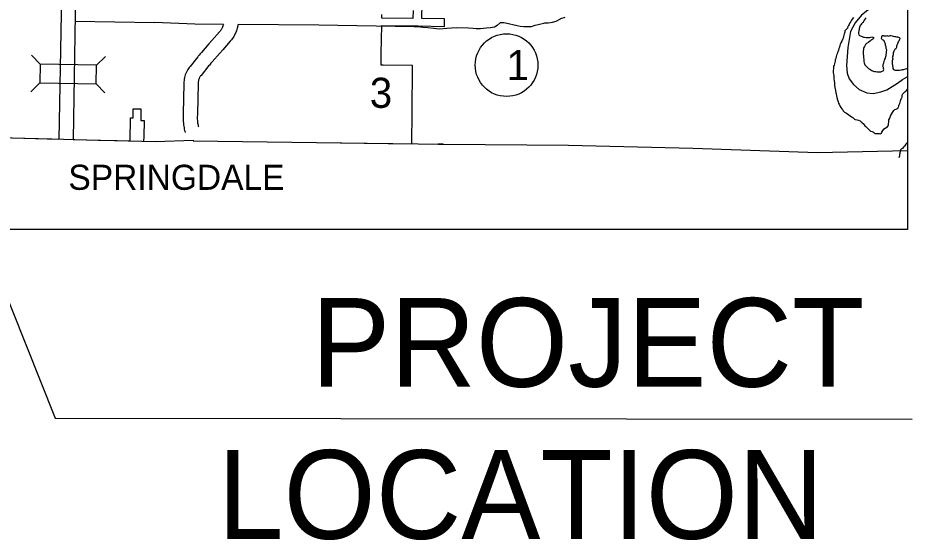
# Model space of a CAD drawing. Extents: x 670147 to 673275, y 705573 to 707613.
# Drawn here: x 670561.9 to 670844.4, y 706894.6 to 707059.4 of the extents above; entities that cross this region are included whole.
import ezdxf

# ---------------------------------------------------------------- set-up
doc = ezdxf.new("R2010")
doc.units = 0
for name, color, linetype in [('10', 7, 'Continuous'), ('15', 7, 'Continuous'), ('2', 7, 'Continuous'), ('20', 7, 'Continuous'), ('27', 7, 'Continuous'), ('3', 7, 'Continuous'), ('6', 7, 'Continuous'), ('9', 7, 'Continuous'), ('Default', 7, 'Continuous'), ('R_NoPlot', 7, 'Continuous')]:
    doc.layers.add(name, color=color, linetype=linetype)

msp = doc.modelspace()

# ---------------------------------------------------------------- linework, layer by layer
at = {"layer": '10'}
for points in [[(670714.38, 707057.94), (670714.95, 707057.96), (670715.35, 707057.98), (670715.96, 707057.82), (670719.66, 707056.95), (670720.57, 707056.8), (670721.72, 707056.67), (670722.83, 707056.67), (670724.1, 707056.72), (670725.29, 707057.05), (670726.28, 707057.33), (670728.01, 707057.78), (670728.36, 707057.87), (670728.75, 707057.89), (670729.38, 707057.86), (670730.13, 707057.94), (670730.81, 707058.02), (670731.9, 707058.41), (670733.05, 707059.03), (670733.26, 707059.12), (670733.45, 707059.2), (670734.82, 707059.61)], [(670580.04, 707058.39), (670605.11, 707057.96)], [(670626.83, 707057.3), (670617.83, 707057.37), (670605.05, 707057.96)], [(670626.61, 707056.66), (670626.51, 707056.43), (670626.42, 707056.24), (670626.33, 707056.05), (670626.22, 707055.86), (670626.09, 707055.65), (670625.95, 707055.44), (670625.79, 707055.24), (670625.71, 707055.13), (670625.6, 707055.01), (670623.21, 707052.28), (670622.27, 707051.22), (670619.86, 707048.47), (670619.46, 707048.01), (670619.17, 707047.66), (670618.89, 707047.32), (670618.75, 707047.15), (670616.28, 707044.09), (670616.17, 707043.95), (670616.02, 707043.76), (670615.78, 707043.43), (670615.56, 707043.08), (670615.34, 707042.71), (670615.14, 707042.3), (670614.95, 707041.88), (670614.79, 707041.44), (670614.66, 707041), (670614.55, 707040.55), (670614.46, 707040.1), (670614.4, 707039.64), (670614.37, 707039.2), (670614.37, 707039.05), (670614.37, 707039.04), (670614.36, 707038.97), (670614.35, 707038.42), (670614.24, 707034.26), (670614.22, 707033.72), (670614.11, 707029.41), (670614.09, 707028.82), (670614.08, 707028.34), (670614.07, 707027.8), (670614.09, 707027.24), (670614.12, 707026.68), (670614.17, 707026.16)], [(670626.83, 707057.3), (670626.68, 707056.85), (670626.58, 707056.58)], [(670631.45, 707057.27), (670631.18, 707056.18), (670631.07, 707055.78), (670630.93, 707055.36), (670630.79, 707055)], [(670714.38, 707057.94), (670713.29, 707056.97), (670712.43, 707056.47), (670711.21, 707056.27), (670709.96, 707056.11), (670708, 707055.97), (670706.7, 707055.99), (670705.69, 707056.05), (670704.19, 707056.2), (670700.59, 707056.28), (670698.91, 707056.15), (670697.35, 707056.02), (670695.23, 707055.89), (670694.16, 707055.92), (670693.15, 707056.02), (670691.36, 707056.23), (670689.83, 707056.37), (670689.08, 707056.48), (670687.08, 707056.61), (670656.97, 707057.07), (670631.45, 707057.27)], [(670630.76, 707054.91), (670630.63, 707054.6), (670630.46, 707054.25), (670630.29, 707053.91), (670630.09, 707053.57), (670629.86, 707053.19), (670629.6, 707052.82), (670629.34, 707052.47), (670629.17, 707052.25), (670629, 707052.06), (670626.59, 707049.31), (670625.65, 707048.25), (670623.25, 707045.51), (670622.89, 707045.09), (670622.64, 707044.79), (670622.38, 707044.48), (670622.26, 707044.33), (670619.78, 707041.26), (670619.69, 707041.15), (670619.62, 707041.06), (670619.5, 707040.89), (670619.4, 707040.74), (670619.31, 707040.57), (670619.21, 707040.39), (670619.13, 707040.2), (670619.06, 707040), (670619, 707039.8), (670618.95, 707039.6), (670618.91, 707039.4), (670618.88, 707039.19), (670618.87, 707038.96), (670618.86, 707038.92), (670618.86, 707038.85), (670618.85, 707038.3), (670618.74, 707034.14), (670618.72, 707033.6), (670618.61, 707029.29), (670618.59, 707028.69), (670618.58, 707028.25), (670618.57, 707027.83), (670618.58, 707027.42), (670618.61, 707027.01), (670618.65, 707026.57)], [(670614.17, 707026.09), (670614.23, 707025.66), (670614.3, 707025.2), (670614.38, 707024.74), (670614.47, 707024.28), (670614.58, 707023.83), (670614.7, 707023.4)], [(670618.64, 707026.64), (670618.69, 707026.27), (670618.74, 707025.94), (670618.8, 707025.6), (670618.87, 707025.27), (670618.92, 707025.04)], [(670614.71, 707023.37), (670614.72, 707023.33), (670614.76, 707023.18)]]:
    msp.add_lwpolyline(points, dxfattribs=at)
at = {"layer": '15'}
for points in [[(670576.52, 707129.64), (670576.32, 707100.63), (670575.55, 707060.68), (670574.89, 707021.12)], [(670581.02, 707129.6), (670580.82, 707100.57), (670580.05, 707060.6), (670579.39, 707021)]]:
    msp.add_lwpolyline(points, dxfattribs=at)
at = {"layer": '2'}
for points in [[(670842.89, 707067.82), (670842.6, 707067.64), (670836.57, 707064.43), (670833.58, 707063.2), (670831.77, 707062.54), (670830.37, 707061.79), (670828.34, 707060.25), (670826.36, 707057.83), (670824.91, 707055.1), (670824.08, 707050), (670823.59, 707044.36), (670823.89, 707041.99), (670824.47, 707040.18), (670825.82, 707038.37), (670827.66, 707036.84), (670830.09, 707035.76), (670832.09, 707035.54), (670834.44, 707036.01), (670836.33, 707036.7), (670839.7, 707038.77), (670841.3, 707040), (670842.82, 707040.76), (670842.89, 707040.79)], [(670483.51, 707023.32), (670498.06, 707023.16), (670537.81, 707022.16), (670574.89, 707021.12)], [(670579.39, 707021), (670605.42, 707020.34)], [(670605.42, 707020.34), (670617.29, 707020.81)], [(670617.29, 707020.81), (670617.29, 707020.62)], [(670617.29, 707020.62), (670656.28, 707020.03), (670696.3, 707019.49), (670735.86, 707019.17), (670775.08, 707018.25), (670814.5, 707016.94), (670842.89, 707017.55)]]:
    msp.add_lwpolyline(points, dxfattribs=at)
at = {"layer": '20'}
for p, q in [((670568.95, 707044.79), (670566.2, 707047.63)), ((670586.77, 707044.49), (670589.62, 707047.24)), ((670568.85, 707038.85), (670566.01, 707036.1)), ((670586.67, 707038.55), (670589.42, 707035.71))]:
    msp.add_line(p, q, dxfattribs=at)
msp.add_lwpolyline([(670568.85, 707038.85), (670586.67, 707038.55), (670586.77, 707044.49), (670568.95, 707044.79)], close=True, dxfattribs=at)
at = {"layer": '27'}
msp.add_circle((670716.27, 707044.49), 9.9, dxfattribs=at)
at = {"layer": '3'}
msp.add_lwpolyline([(670696.27, 707019.49), (670694.62, 707019.52)], dxfattribs=at)
at = {"layer": '6'}
for points in [[(670686.36, 707019.63), (670686.37, 707021.43), (670686.39, 707023.25), (670686.41, 707026.14), (670686.44, 707029.51), (670686.44, 707030.2), (670686.43, 707031.88), (670686.43, 707032.26), (670686.46, 707034.21), (670686.46, 707034.58), (670686.5, 707039.02), (670686.51, 707039.37), (670686.54, 707044.32), (670677.28, 707044.46), (670676.64, 707044.47), (670676.68, 707048.15), (670676.83, 707057.04), (670686.68, 707056.88), (670687.78, 707056.87), (670688.34, 707056.86), (670696.66, 707056.72), (670696.67, 707058.41), (670696.67, 707058.72), (670696.66, 707058.98), (670696.65, 707059.1), (670689.54, 707059.17), (670689.61, 707064.05)], [(670686.8, 707061.78), (670686.7, 707059.2), (670676.86, 707059.3), (670676.87, 707060.44)], [(670597.42, 707020.54), (670597.51, 707027.89), (670598.33, 707027.86), (670598.36, 707030.74), (670599.02, 707030.72), (670599.55, 707030.71), (670600.69, 707030.69), (670600.78, 707030.69), (670600.72, 707027.03), (670601.56, 707027.02), (670601.77, 707027.01), (670601.68, 707021.85), (670601.62, 707020.44)], [(670547.03, 707021.9), (670572.67, 707021.18), (670587.25, 707020.8), (670593.29, 707020.65), (670597.42, 707020.54)], [(670601.62, 707020.44), (670605.42, 707020.34), (670617.29, 707020.81), (670617.29, 707020.62), (670656.28, 707020.03), (670686.36, 707019.63)], [(670694.62, 707019.52), (670694.62, 707019.56), (670694.8, 707019.56), (670696.27, 707019.54), (670696.27, 707019.49)]]:
    msp.add_lwpolyline(points, dxfattribs=at)
at = {"layer": '9'}
for points in [[(670825.88, 707059.57), (670825.45, 707059.01), (670825.18, 707058.66), (670824.96, 707058.25), (670824.71, 707057.83), (670824.51, 707057.27)], [(670829.87, 707059.4), (670829.5, 707059.11), (670829.17, 707058.64), (670828.99, 707058.21), (670828.9, 707057.97), (670828.71, 707057.8), (670828.35, 707057.54)], [(670824.07, 707056.63), (670823.94, 707056.2), (670823.77, 707055.99), (670823.55, 707055.78), (670823.39, 707055.61), (670823.21, 707055.4), (670823.16, 707055.36), (670823.15, 707055.09), (670823.15, 707054.91), (670823.02, 707054.62), (670822.88, 707054.38), (670822.78, 707053.97), (670822.68, 707053.54), (670822.56, 707053.04), (670822.41, 707052.57), (670822.13, 707052.04), (670821.85, 707051.5), (670821.69, 707051.14), (670821.51, 707050.64), (670821.39, 707050.16), (670821.26, 707049.74), (670821.09, 707049.21), (670820.98, 707048.87), (670820.81, 707048.43), (670820.64, 707048.01), (670820.5, 707047.59), (670820.39, 707047.16), (670820.23, 707046.59), (670820.11, 707046.16), (670820.04, 707045.72), (670819.94, 707045.28), (670819.84, 707044.85), (670819.76, 707044.5), (670819.57, 707044.14), (670819.5, 707043.72), (670819.49, 707043.33), (670819.44, 707042.86), (670819.43, 707042.48), (670819.43, 707042.11), (670819.53, 707041.6), (670819.59, 707041.16), (670819.59, 707040.65), (670819.66, 707040.14), (670819.75, 707039.57), (670819.8, 707038.78), (670819.88, 707038.13), (670819.91, 707037.41), (670820.02, 707036.88), (670820.16, 707036.49), (670820.28, 707035.77), (670820.34, 707035.47), (670820.48, 707034.81), (670820.61, 707034.27), (670820.79, 707033.51), (670821.02, 707032.92), (670821.14, 707032.44), (670821.29, 707032.16), (670821.52, 707031.68), (670821.84, 707031.1), (670822.17, 707030.69), (670822.43, 707030.35), (670822.59, 707030.04), (670822.87, 707029.74), (670823, 707029.66), (670823.59, 707029.32), (670824.36, 707028.82), (670824.78, 707028.53), (670825.24, 707028.19), (670825.67, 707027.95), (670825.91, 707027.65), (670826.16, 707027.46), (670826.42, 707027.33), (670827, 707027.21), (670827.42, 707027.11), (670827.92, 707026.87), (670828.21, 707026.66), (670828.49, 707026.46), (670828.64, 707026.28), (670828.93, 707026.01), (670829.19, 707025.65), (670829.46, 707025.35), (670829.75, 707025.07), (670829.96, 707024.87), (670830.35, 707024.5), (670830.74, 707024.14), (670830.97, 707023.84), (670831.27, 707023.66), (670831.7, 707023.52), (670832.21, 707023.28), (670832.55, 707022.95), (670833.09, 707022.9), (670833.58, 707022.87), (670833.96, 707022.86), (670834.29, 707022.81), (670834.65, 707022.97), (670834.79, 707023.3), (670835.09, 707023.8), (670835.52, 707024.33), (670835.98, 707024.64), (670836.36, 707024.84), (670836.84, 707025.28)], [(670824.51, 707057.27), (670824.32, 707056.97), (670824.14, 707056.76), (670824.07, 707056.63)], [(670827.82, 707056.68), (670827.66, 707056.05), (670827.6, 707055.6), (670827.53, 707055.28), (670827.41, 707054.86), (670827.41, 707054.44), (670827.56, 707054.1), (670827.76, 707053.86), (670828.03, 707053.69), (670828.28, 707053.62), (670828.61, 707053.52), (670828.96, 707053.32), (670829.35, 707053.27), (670829.83, 707053.18), (670830.39, 707053.21), (670830.9, 707053.26), (670831.3, 707053.31), (670831.64, 707053.37), (670831.94, 707053.3), (670832.12, 707053.2), (670832.23, 707053.09), (670832.14, 707052.91), (670831.92, 707052.7), (670831.69, 707052.5), (670831.37, 707052.21), (670831.1, 707052.06), (670830.63, 707051.71), (670830.4, 707051.56), (670830.13, 707051.41), (670829.92, 707051.27), (670829.62, 707051.01), (670829.49, 707050.76), (670829.34, 707050.35), (670829.15, 707050.05), (670829.06, 707049.7), (670829.03, 707049.45), (670828.94, 707048.92), (670828.92, 707048.41), (670828.93, 707047.96), (670828.98, 707047.46), (670829, 707047.06), (670829.03, 707046.77), (670829.09, 707046.41), (670829.11, 707046.08), (670829.13, 707045.62), (670829.22, 707045.18), (670829.3, 707044.87), (670829.42, 707044.58), (670829.6, 707044.33), (670829.8, 707044.12), (670830.05, 707044), (670830.29, 707043.75), (670830.62, 707043.45), (670830.97, 707043.21), (670831.33, 707042.96), (670831.63, 707042.76), (670832.1, 707042.59), (670832.44, 707042.45), (670832.86, 707042.44), (670833.3, 707042.36), (670833.85, 707042.34), (670834.47, 707042.42), (670834.89, 707042.53), (670835.17, 707042.64), (670835.35, 707042.82), (670835.48, 707043.15), (670835.36, 707043.39), (670835.3, 707043.71), (670835.18, 707043.99), (670835.12, 707044.19), (670835.21, 707044.4), (670835.26, 707044.7), (670835.32, 707044.92), (670835.41, 707045.21), (670835.51, 707045.65), (670835.68, 707046.02), (670835.78, 707046.34), (670835.96, 707046.73), (670836.04, 707047.23), (670836.15, 707047.57), (670836.2, 707048), (670836.28, 707048.31), (670836.32, 707048.7), (670836.33, 707049.17), (670836.3, 707049.45), (670836.21, 707049.93), (670836.12, 707050.28), (670836.05, 707050.52), (670836.01, 707050.79), (670835.96, 707051.12), (670835.84, 707051.4), (670835.76, 707051.66), (670835.69, 707051.87), (670835.58, 707052.11), (670835.44, 707052.29), (670835.25, 707052.38), (670834.99, 707052.52), (670834.75, 707052.66), (670834.65, 707052.87), (670834.7, 707053.14), (670834.79, 707053.36)], [(670828.35, 707057.54), (670828.17, 707057.16), (670827.99, 707056.95), (670827.82, 707056.68)], [(670834.79, 707053.36), (670834.85, 707053.58), (670834.97, 707053.79), (670835.19, 707053.79), (670835.46, 707053.76), (670835.73, 707053.72), (670835.97, 707053.7), (670836.21, 707053.69), (670836.41, 707053.8), (670836.59, 707053.72), (670836.84, 707053.66), (670837.1, 707053.7), (670837.38, 707053.82), (670837.64, 707053.82), (670838.1, 707053.7), (670838.39, 707053.61), (670838.75, 707053.53), (670839.09, 707053.48), (670839.39, 707053.37), (670839.74, 707053.37), (670840.1, 707053.28), (670840.29, 707053.22), (670840.43, 707053.15), (670840.52, 707052.97), (670840.49, 707052.8), (670840.43, 707052.58), (670840.31, 707052.4), (670840.14, 707052.09), (670839.97, 707051.81), (670839.83, 707051.54), (670839.74, 707051.25), (670839.68, 707051.02), (670839.57, 707050.84), (670839.47, 707050.51), (670839.4, 707050.17), (670839.41, 707050), (670839.36, 707049.81), (670839.18, 707049.62), (670838.95, 707049.41), (670838.82, 707049.23), (670838.69, 707049.08), (670838.55, 707048.75), (670838.42, 707048.51), (670838.35, 707048.15), (670838.33, 707047.77), (670838.32, 707047.47), (670838.29, 707047.14), (670838.05, 707047), (670838.2, 707046.78), (670838.25, 707046.46), (670838.15, 707046.19), (670838.11, 707045.87), (670838.11, 707045.53), (670838.09, 707045.23), (670838.08, 707044.93), (670838.13, 707044.6), (670838.21, 707044.22), (670838.24, 707043.73), (670838.3, 707043.47), (670838.47, 707043.08), (670838.71, 707042.99), (670838.96, 707042.92), (670839.47, 707042.89), (670839.92, 707042.85), (670840.43, 707042.89), (670840.97, 707042.95), (670841.33, 707043.06), (670841.75, 707043.08), (670842.23, 707043.29), (670842.65, 707043.43), (670842.89, 707043.5)], [(670836.84, 707025.28), (670836.88, 707025.54), (670836.94, 707026.02), (670836.98, 707026.45), (670837.01, 707026.92), (670837.06, 707027.27), (670837.36, 707027.79), (670837.51, 707028.37), (670837.67, 707028.68), (670837.86, 707029.01), (670838.16, 707029.51), (670838.38, 707029.8), (670838.6, 707030.16), (670838.93, 707030.43), (670839.37, 707030.63), (670839.8, 707030.8), (670839.96, 707030.89), (670839.99, 707031.13), (670840.13, 707031.57), (670840.2, 707031.8), (670840.32, 707031.99), (670840.5, 707032.38), (670840.58, 707032.81), (670840.65, 707033.23), (670840.76, 707033.57), (670840.88, 707033.84), (670841.08, 707034.22), (670841.19, 707034.42), (670841.19, 707034.75), (670841.23, 707035.02), (670841.47, 707035.47), (670841.72, 707035.7), (670842.08, 707036.02), (670842.36, 707036.26), (670842.63, 707036.5), (670842.89, 707036.89)], [(670842.4, 707019.52), (670842.13, 707019.2), (670841.96, 707018.9), (670841.82, 707018.67), (670841.58, 707018.48), (670841.31, 707018.22), (670841.08, 707018.11), (670840.87, 707017.96), (670840.67, 707017.71), (670840.6, 707017.4), (670840.56, 707017.16), (670840.5, 707016.79), (670840.47, 707016.59), (670840.43, 707016.25), (670840.34, 707015.82), (670840.24, 707015.51), (670840.13, 707015.24)], [(670842.89, 707020.15), (670842.65, 707019.85), (670842.4, 707019.52)]]:
    msp.add_lwpolyline(points, dxfattribs=at)
at = {"layer": 'Default'}
msp.add_lwpolyline([(670496.38, 707126.84), (670573.69, 706933.06), (670844.37, 706932.74)], dxfattribs=at)
at = {"layer": 'R_NoPlot'}
msp.add_lwpolyline([(670257.19, 707521.73), (670842.89, 707521.73), (670842.89, 706992.57), (670257.19, 706992.57)], close=True, dxfattribs=at)

# ---------------------------------------------------------------- texts
at = {"layer": '2'}
msp.add_text('SPRINGDALE', height=7.92, dxfattribs=at).set_placement((670577.86, 707005.12))
at = {"layer": '27'}
msp.add_text('1', height=9.5, dxfattribs=at).set_placement((670716.27, 707039.74))
msp.add_text('3', height=9.5, rotation=359.9, dxfattribs=at).set_placement((670673.06, 707031.01))
at = {"layer": 'Default'}
for s, p in [('PROJECT', (670654.57, 706942.95)), ('LOCATION', (670625, 706894.95))]:
    msp.add_text(s, height=28, dxfattribs=at).set_placement(p)

doc.saveas('drawing.dxf')
